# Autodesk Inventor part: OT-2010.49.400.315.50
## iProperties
Category: PARTsolutions
Created: 2012-10
Part Number: OT-2010.49.400.315.50
Catalog Web Link: www.cadenas.de
Description: 2010.Oberteil - Oberteil f. SG 2010.
Document SubType Name: Modeling
Designer: PARTsolutions
Density: 1 g/cm^3
NB: OT-2010.49.400.315.50
NN: 2010.Oberteil
NT: Oberteil f. SG 2010.
NBSYN: OT-2010.$PW.$BF..$AM..$C2.
LINA: OT-2010.49.400.315.50
BF: 9
PW: 4
PK: 1
A1: 400.000
B1: 315.000
LAF: 2
C2: 50
E1: 310.000
D1: 30.000
D2: 32.000
D3: 48.000
E2: 225.000
E3: 270.000
E4: 313.000
C2INHALT: 50.000
AM: 400.315
KT: X
SUPPLIER: FIBRO
ARTICLENO: OT-2010.49.400.315.50
BOMINFO: OT-2010.49.400.315.50
CREATOR: CADENAS GmbH
PSOL_IDENT_0: {\\10.0.0.251\data_v9\23d-libs\fibro\normalien\a\a02\a02_00\ot_2010_2081.prj},212 {VTYP=3D},{NB=OT-2
PSOL_IDENT_1: 010.49.400.315.50},{LINA=OT-2010.49.400.315.50},{NN=2010.Oberteil},{DATE=10.11.2011 06:58:49},{GEOMD
PSOL_IDENT_2: ATE=10.11.2011 06:52:00},{VERSION=v1},{LINEID=180},{LINESUBID=-1},{WBVAR=BF,PW,PK,LAF,C2,AM}  {NB=OT
PSOL_IDENT_3: -2010.49.400.315.50},{LINA=OT-2010.49.400.315.50},{KT=X},{BF=9},{PW=4},{PK=1},{A1=400.000},{B1=315.0
PSOL_IDENT_4: 00},{LAF=2},{C2=50},{E1=310.000},{D1=30.000},{D2=32.000},{D3=48.000},{E2=225.000},{E3=270.000},{E4=3
PSOL_IDENT_5: 13.000},{C2INHALT=50},{AM=400.315}
ipwModelExtentsX: 400
ipwModelExtentsY: 50
ipwModelExtentsZ: 315
ipwMass: 5.9
ipwArea: 0.3 m^2
ipwVolume: 5.9
Title: OT-2010.49.400.315.50
Author: Cadenas PARTsolutions
Comments: Oberteil f. SG 2010.
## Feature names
1. Extrusion1
2. Extrusion2
3. Extrusion3
4. Extrusion4
5. Extrusion5
